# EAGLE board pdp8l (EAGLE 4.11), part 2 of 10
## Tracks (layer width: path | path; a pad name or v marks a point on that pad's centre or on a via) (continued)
B_BK  (via drill 0.61) (continued)
  Route2 0.203: v319.84,229.06 329.59,238.81 329.59,240.44 330,240.84 330,242.06 331.62,243.69 A10.L2 | v340.97,108.76 327.96,95.76 v327.56,95.76
  Route15 0.203: v336.91,86.41 v327.56,95.76 322.68,100.63 322.68,104.29 C11.M2 | v352.75,174.19 352.75,174.6 329.18,198.17 328.78,198.17 327.96,198.98 327.96,199.39 322.27,205.08 322.27,211.58 305.61,228.24 306.43,229.06 308.86,229.06 A12.S2
  Bottom 0.203: v319.84,229.06 318.21,227.43 310.9,227.43 310.08,228.24 A12.S2 | v336.91,86.41 338.94,84.38 355.6,84.38 356.01,84.78 359.26,84.78 360.07,83.97 365.76,83.97 366.98,82.75 369.42,82.75 C07.V2 | v346.66,150.22 346.25,150.62 343.81,150.62 342.6,149.4 v342.6,147.78
B_CA  (via drill 0.61)
  Top 0.203: v310.49,249.78 310.9,249.38 310.9,246.94 309.68,245.72 309.68,242.06 A12.M2 | v338.12,248.56 338.12,244.91 A10.L1 | v425.09,51.46 425.09,10.82 427.13,10.82 428.35,12.04 428.35,12.45 432.82,12.45 D02.V2 | v419,135.59 419,161.59 416.15,164.44 416.15,172.57 419.4,175.82 419.4,204.67 420.22,205.49 420.22,214.83 v419.81,215.24
  Route2 0.203: v425.09,51.46 425.09,53.09 434.85,62.84 434.85,68.53 v452.73,86.41 | v343.81,247.75 343.41,247.75 341.78,246.13 340.56,246.13 338.94,244.5 A10.L1
  Route15 0.203: v452.73,86.41 452.73,86.82 451.1,88.44 451.1,101.04 419.4,132.74 419.4,135.18 v419,135.59 | v419.81,215.24 415.75,219.3 415.75,219.71 399.08,236.37 394.21,236.37 v383.64,246.94
  Bottom 0.203: v310.49,249.78 310.9,249.38 337.31,249.38 v338.12,248.56 | v383.64,246.94 383.24,246.53 379.98,246.53 379.58,246.13 370.23,246.13 367.39,248.97 347.07,248.97 345.85,247.75 v343.81,247.75
B_EXECUTE  (via drill 0.61)
  Top 0.203: A12.N1 312.52,238.81 311.71,239.62 311.71,243.28 311.3,243.69 311.3,255.88 309.68,257.5 309.68,259.54 A12.E2 309.27,261.16 308.05,262.38 308.05,266.45 303.99,266.45 A13.C1 | 330.4,248.16 330.4,259.94 331.62,261.16 331.62,262.79 A10.D2 | 330.4,228.65 330.4,248.16 | 330.4,228.65 330.4,218.49 331.62,217.27 331.62,202.23 330.4,201.02 330.4,192.89 330.81,192.48 330.81,188.82 331.62,188.01 B10.F2 | 330.4,248.16 v330.81,248.16 | 330.4,228.65 v330.81,228.65 | v336.91,35.2 336.5,35.61 336.5,71.78 v336.91,72.19 | v323.09,73.41 323.49,73.81 323.49,88.85 322.27,90.07 322.27,91.29 C11.S2 | v307.24,128.68 307.64,128.27 307.64,109.98 306.43,108.76 C12.L2 | v343,151.84 343,151.03 348.29,151.03 349.5,152.25 349.5,168.91 350.32,169.72 350.32,174.19 B09.L1 | v283.67,131.93 285.29,131.93 285.29,128.68 v285.29,128.27
  Route2 0.203: v330.81,228.65 329.18,228.65 A11.S1 | v285.29,128.27 284.48,127.46 284.48,124.61 C14.E2 | v343,151.84 342.6,151.84 341.78,151.03 337.72,151.03 336.91,150.22 336.91,149.4 323.49,135.99 323.49,135.59 v322.27,134.37
  Route15 0.203: A11.S1 327.96,229.06 325.93,229.06 317.81,237.19 313.74,237.19 313.33,237.59 A12.N1 | v348.29,174.6 347.88,174.6 339.75,182.73 338.53,182.73 335.69,185.57 334.06,185.57 332.44,187.2 B10.F2 | C11.S2 321.46,92.1 320.65,92.1 319.84,92.91 317.81,92.91 309.27,101.45 309.27,103.07 308.05,104.29 308.05,105.51 306.43,107.14 C12.L2 | v336.91,35.2 343.81,28.3 343.81,25.86 D09.R2
  Bottom 0.203: A13.E2 297.49,259.94 298.3,259.13 308.05,259.13 308.86,259.94 A12.E2 | v348.29,174.6 350.32,174.6 B09.L1 | v330.81,248.16 334.47,248.16 A10.K2 | v285.29,128.27 285.7,128.68 v307.24,128.68 314.15,128.68 315.37,129.9 C12.C1 | v336.91,72.19 336.5,72.59 323.9,72.59 v323.09,73.41 | v322.27,134.37 321.06,135.59 318.21,135.59 316.99,134.37 313.74,134.37 313.33,134.77 304.39,134.77 301.55,131.93 291.8,131.93 291.39,132.33 288.54,132.33 288.14,131.93 v283.67,131.93
B_FETCH  (via drill 0.61)
  Top 0.203: v304.39,207.11 v304.39,257.91 | v352.75,207.11 352.75,192.48 353.97,191.26 B09.E1 | v303.17,125.83 303.17,129.49 C13.C1 | v343.41,98.6 342.6,99.42 342.6,109.17 341.38,110.39 C10.K1 | v336.91,113.23 336.91,125.02 338.12,126.24 C10.D1 | v321.87,42.93 323.49,44.55 323.49,66.5 325.12,68.12 325.12,80.72 324.31,81.53 324.31,92.91 | 324.31,92.91 324.31,93.73 325.12,94.54 C11.R1 325.93,95.76 327.15,96.98 327.15,103.89 326.75,104.29 326.75,116.89 v326.34,117.3 | v281.63,92.1 281.63,94.13 281.23,94.54 C14.R2 | 324.31,92.91 v325.12,92.91 | v331.62,170.13 330.4,168.91 v330.4,125.83
  Route2 0.203: v351.54,191.26 338.12,177.85 335.69,177.85 B10.K2 334.87,177.04 334.87,173.38 v331.62,170.13
  Route15 0.203: 336.91,112.83 338.94,112.83 340.56,111.2 C10.K1 | 336.91,112.83 331.22,112.83 329.18,114.86 329.18,116.89 C11.H1 327.96,117.3 v326.34,117.3 | v336.91,113.23 336.91,112.83
  Bottom 0.203: v351.54,191.26 351.94,190.86 353.57,190.86 B09.E1 | v304.39,257.91 301.14,257.91 300.74,257.5 A13.F1 | v304.39,207.11 304.8,206.7 310.08,206.7 310.49,206.3 314.96,206.3 315.37,206.7 352.35,206.7 v352.75,207.11 | v303.17,125.83 303.58,125.42 330.4,125.42 | 330.4,125.42 331.22,125.42 331.62,125.83 336.91,125.83 337.72,126.64 C10.D1 | v343.41,98.6 347.07,98.6 C09.P2 | v321.87,42.93 314.55,42.93 313.33,44.15 D12.J1 | v281.63,92.1 282.85,93.32 324.71,93.32 v325.12,92.91 | v330.4,125.83 330.4,125.42
B_INHIBIT  (via drill 0.61)
  Top 0.203: 165,274.17 171.09,280.26 171.09,280.67 171.5,281.08 175.97,281.08 175.97,273.76 A23.A1 | 165,274.17 164.19,273.36 A24.A1 | v234.9,205.49 234.9,198.98 235.31,198.58 235.31,161.19 237.74,158.75 237.74,94.54 237.34,94.13 237.34,93.32 237.74,92.91 237.74,44.55 242.21,44.55 D17.J2 | v176.38,207.11 176.38,203.86 B23.A1 | 165,274.17 167.84,271.32 167.84,241.25 165,238.4 165,205.08 163.78,203.86 B24.A1
  Bottom 0.203: 176.38,205.49 166.22,205.49 164.19,203.45 B24.A1 | v234.9,205.49 176.38,205.49 | 176.38,205.49 v176.38,207.11
B_MEM_ENABLE  (via drill 0.61)
  Top 0.203: D25.N2 141.02,32.36 139.8,33.58 v139.8,52.68 139.8,53.09 139.8,99.82 141.02,101.04 C25.N2 141.02,102.26 139.8,103.48 139.8,117.3 142.65,120.14 142.65,123.8 139.8,126.64 139.8,127.46 140.61,128.27 144.27,128.27 144.27,124.61 C25.E2 | C18.D2 229.62,127.46 228.8,128.27 228.8,154.28 229.62,155.09 B18.T2 230.02,156.31 230.02,159.16 228.8,160.38 228.8,224.18 229.62,224.99 A18.T2 | A23.E2 169.88,259.54 168.66,258.32 168.66,240.44 167.03,238.81 A23.N2 166.22,237.59 165.41,236.78 165.41,200.61 157.28,192.48 157.28,191.26 B24.E2 156.46,190.04 155.65,189.23 155.65,170.13 154.43,168.91 B24.N2 | v153.62,122.58 153.62,126.24 C24.D2 | C23.D2 167.03,127.46 167.84,128.27 167.84,166.88 167.03,167.69 B23.N2
  Route15 0.203: D17.L1 249.12,38.86 249.12,40.08 234.09,55.12 232.46,55.12 230.84,56.74 D18.D2
  Bottom 0.203: D17.E1 251.97,54.3 250.75,55.52 232.05,55.52 230.84,56.74 D18.D2 229.62,56.74 228.8,55.93 219.05,55.93 218.24,56.74 D19.D2 217.02,57.56 216.21,58.37 171.91,58.37 171.09,57.56 167.44,57.56 D23.D2 166.22,57.56 165.41,58.37 155.25,58.37 154.43,57.56 D24.D2 153.21,57.15 151.18,55.12 145.9,55.12 145.09,54.3 D25.E2 143.87,53.49 140.61,53.49 v139.8,52.68 | 216.21,226.62 206.04,226.62 205.23,225.81 A20.T2 | 216.21,226.62 217.02,225.81 A19.T2 | 216.21,226.62 228.8,226.62 229.62,225.81 A18.T2 230.84,225.81 231.65,226.62 241.4,226.62 242.21,225.81 A17.T2 | C18.D2 229.62,127.46 228.8,128.27 219.46,128.27 218.24,127.05 C19.D2 217.02,127.05 213.36,127.05 212.14,128.27 168.66,128.27 167.44,127.05 C23.D2 166.22,126.64 165.41,125.83 155.25,125.83 154.43,126.64 C24.D2 | 216.21,156.72 206.04,156.72 205.23,155.91 B20.T2 | 216.21,156.72 217.02,155.91 B19.T2 | 216.21,156.72 228.8,156.72 229.62,155.91 B18.T2 | A24.E2 157.68,259.94 158.5,259.13 167.84,259.13 169.06,260.35 A23.E2 | v153.62,122.58 145.9,122.58 145.09,123.39 C25.E2 | B24.N2 154.43,167.69 155.25,166.88 164.19,166.88 165,167.69 166.22,167.69 B23.N2 | B24.E2 157.68,190.86 158.5,191.67 168.25,191.67 169.06,190.86 B23.E2
B_SET  (via drill 0.61)
  Top 0.203: v28.85,244.91 25.6,248.16 25.6,264.41 23.98,266.04 A35.C1 | v239.78,143.31 241,142.09 241,70.16 238.56,67.72 v238.56,45.36 | v314.96,46.18 314.55,45.77 314.55,24.23 315.77,23.01 D12.S1
  Route15 0.203: v138.99,243.28 201.98,180.29 202.79,180.29 v239.78,143.31
  Bottom 0.203: v28.85,244.91 30.89,242.88 138.58,242.88 v138.99,243.28 | v238.56,45.36 239.37,46.18 v314.96,46.18 | D10.T2 331.22,19.36 329.59,20.98 319.84,20.98 319.02,21.79 316.59,21.79 D12.S1
B_WC  (via drill 0.61)
  Route2 0.203: v335.28,133.96 347.88,146.56 347.88,148.18 v348.69,149
  Route15 0.203: v335.28,133.96 341.38,127.86 341.38,125.83 371.86,95.35 371.86,91.29 372.26,90.88 372.26,90.07 379.17,83.16 379.17,81.53 403.56,57.15 403.56,53.09 433.22,23.42 433.22,19.76 D02.T2 | v348.69,149 348.69,149.4 340.16,157.94 340.16,162 338.94,163.22 337.31,163.22 335.69,164.85 B10.P2
BEMA  (via drill 0.61)
  Top 0.203: v330.4,77.88 330.4,83.16 330.81,83.57 330.81,88.04 331.22,88.44 C10.T2 | v13.01,125.83 13.01,154.28 13.82,155.09 B35.T2
  Route2 0.203: v330.4,77.88 330.4,77.06 311.3,57.96 311.3,57.15 310.9,56.74 307.64,56.74 306.83,55.93 274.73,55.93 273.91,55.12 269.04,55.12 262.94,49.02 242.21,49.02 v241.81,48.62
  Route15 0.203: v178.82,49.02 133.71,94.13 133.71,96.16 132.08,97.79 C26.P2
  Bottom 0.203: v241.81,48.62 241.4,49.02 v178.82,49.02 | v13.01,125.83 13.01,122.99 12.19,122.99 8.13,118.92 4.06,118.92 3.25,118.11 3.25,96.98 13.82,96.98 16.66,99.82 26.82,99.82 29.67,96.98 39.42,96.98 42.27,99.82 115.42,99.82 118.26,96.98 130.45,96.98 131.27,97.79 C26.P2
BREAK
  Top 0.203: D10.V2 331.22,13.26 330,14.48 330,29.11 321.06,38.05 321.06,46.18 321.87,46.99 D11.H2
BREAK\  (via drill 0.61)
  Top 0.203: v116.64,111.61 116.64,109.17 116.23,108.76 C27.L2 | v339.34,67.72 339.34,14.07 338.53,13.26 D10.V1 338.53,12.04 342.19,8.38 342.19,5.13 | v372.67,68.53 373.07,68.94 373.07,85.19 C07.U2 | v441.35,31.14 440.94,30.73 440.94,18.14 423.88,1.07 342.19,1.07 342.19,5.13 | v323.49,5.13 342.19,5.13
  Route2 0.203: v441.35,31.14 445.41,35.2 445.41,37.64 D01.L2
  Route15 0.203: v235.31,5.13 186.13,54.3 184.91,54.3 164.59,74.62 164.59,76.66 162.97,78.28 162.56,78.28 128.83,112.01 128.83,113.64 C26.J2
  Bottom 0.203: v116.64,111.61 117.86,112.83 126.8,112.83 128.02,114.05 C26.J2 | v339.34,67.72 339.34,68.94 372.26,68.94 v372.67,68.53 | v235.31,5.13 235.71,5.54 246.69,5.54 247.5,6.35 260.5,6.35 262.13,4.72 292.2,4.72 293.42,5.94 301.14,5.94 302.36,4.72 323.09,4.72 v323.49,5.13
BREAK_OK
  Top 0.203: D12.R2 306.02,25.86 305.21,26.67 305.21,36.83 306.02,37.64 D12.L2 306.02,38.86 306.02,41.3 304.39,42.93 304.39,52.68 303.58,53.49 D13.E1
  Bottom 0.203: D11.M1 327.96,35.2 327.15,36.02 323.09,36.02 322.27,36.83 307.64,36.83 306.83,37.64 D12.L2
BREAK_OK\  (via drill 0.61)
  Top 0.203: v321.46,114.86 321.06,115.27 321.06,131.12 321.87,131.93 v321.87,133.15 | v303.99,95.76 304.39,95.35 304.39,70.97 303.99,70.56 303.99,68.12 304.39,67.72 304.39,58.78 v303.99,58.37
  Route2 0.203: v321.46,114.86 321.06,114.45 319.84,114.45 C11.J2 318.62,113.64 318.62,111.61 309.27,102.26 309.27,101.04 v303.99,95.76
  Bottom 0.203: v321.87,133.15 324.71,133.15 C11.B1 | D13.D1 300.74,57.56 301.55,58.37 v303.99,58.37 317.81,58.37 318.21,58.78 329.59,58.78 330,58.37 335.28,58.37 337.72,55.93 338.53,55.93 340.97,58.37 340.97,59.59 D10.C1
BRK_RQST\  (via drill 0.61)
  Top 0.203: v319.84,134.77 319.84,144.93 320.24,145.34 320.24,154.28 319.43,155.09 B11.T2
  Route2 0.203: v319.84,134.77 318.62,134.77 317.81,133.96 317.81,129.08 316.18,127.46 316.18,126.24 308.05,118.11 308.05,114.05 288.54,94.54 288.54,93.73 284.48,89.66 282.85,89.66 277.57,94.94 269.04,86.41 267.82,86.41 262.53,81.13 243.84,81.13 175.97,13.26 v175.56,13.26
  Route15 0.203: D29.T2 89.81,19.36 87.38,19.36 41.05,65.68 41.05,66.5 36.58,70.97 36.58,81.53 8.94,109.17 6.91,109.17 5.28,110.79 C36.K2
  Bottom 0.203: v175.56,13.26 173.13,10.82 101.6,10.82 93.88,18.54 91.03,18.54 D29.T2
BTP2  (via drill 0.61)
  Top 0.203: v401.12,36.02 403.15,36.02 403.15,42.52 401.93,43.74 D05.J1
  Route15 0.203: v47.14,150.62 47.14,150.22 47.55,149.81 47.55,146.56 v153.21,40.89 | v316.59,32.77 321.06,37.24 321.87,36.42 331.62,36.42 v332.44,35.61
  Bottom 0.203: v47.14,150.62 25.6,150.62 25.6,154.28 26.42,155.09 B34.T2 | v153.21,40.89 157.68,36.42 236.12,36.42 242.21,30.33 264.97,30.33 267.82,33.17 303.58,33.17 303.99,33.58 310.08,33.58 310.49,33.17 316.18,33.17 v316.59,32.77 | v332.44,35.61 333.25,36.42 350.72,36.42 353.57,33.58 388.93,33.58 391.77,36.42 400.71,36.42 v401.12,36.02
BTP3  (via drill 0.61)
  Top 0.203: v212.55,66.5 200.76,78.28 v200.76,79.91
  Route15 0.203: v335.28,64.47 347.07,52.68 348.69,52.68 349.1,52.27 351.54,52.27 365.76,38.05 371.86,44.15 375.51,44.15 D07.J1 | v102.82,87.22 54.05,135.99 54.05,137.62 34.95,156.72 34.95,158.34 13.01,180.29 13.01,181.91 11.38,183.54 B36.H1
  Bottom 0.203: v335.28,64.47 334.87,64.87 330,64.87 327.56,62.43 326.34,62.43 325.93,62.03 317.4,62.03 316.99,62.43 313.74,62.43 313.33,62.03 304.39,62.03 303.99,62.43 301.14,62.43 300.74,62.03 291.8,62.03 291.39,62.43 288.14,62.43 287.73,62.03 279.2,62.03 278.79,62.43 275.54,62.43 275.13,62.03 266.6,62.03 266.19,62.43 262.94,62.43 262.53,62.03 254,62.03 251.16,64.87 241,64.87 240.59,64.47 237.74,64.47 236.93,65.28 213.77,65.28 v212.55,66.5 | v200.76,79.91 126.8,79.91 119.48,87.22 v102.82,87.22
C01V1  (via drill 0.61)
  Top 0.508: v450.7,140.46 450.7,84.38 451.92,83.16 C01.V1 | v108.1,140.46 107.7,140.87 107.7,206.7 104.85,209.55 104.85,229.87 103.63,231.09 A28A.R2
  Bottom 0.508: v450.7,140.46 450.29,140.87 209.3,140.87 208.89,140.46 v108.1,140.46
CA_INCREMENT  (via drill 0.61)
  Top 0.203: v16.26,140.46 16.26,123.39 18.69,120.95 18.69,106.32 17.88,105.51 C35.M2 | v42.67,166.88 42.67,170.94 B33.M2 | v102.01,274.98 101.19,274.17 101.19,232.31 v100.38,231.5
  Route2 0.203: v16.26,140.46 16.26,140.87 20.73,145.34 21.13,145.34 v42.67,166.88 | v100.38,231.5 100.38,231.09 89.81,220.52 88.59,220.52 76.4,208.33 76.4,207.11 44.7,175.41 44.7,173.79 43.08,172.16 B33.M2
  Route15 0.203: v232.05,277.01 244.25,264.82 262.53,264.82 263.75,263.6 264.57,263.6 266.19,261.98 267.82,261.98 280.82,248.97 290.98,248.97 294.23,245.72 300.74,245.72 301.95,244.5 305.61,244.5 A12.L2
  Bottom 0.203: v232.05,277.01 231.65,277.42 175.16,277.42 174.35,276.61 156.06,276.61 154.84,275.39 102.41,275.39 v102.01,274.98
CARRY_INSERT  (via drill 0.61)
  Top 0.203: v249.94,195.73 245.06,200.61 245.06,202.23 241.4,205.89 241.4,266.45 v247.9,272.95 | v288.54,276.2 292.2,276.2 v292.2,273.76 | v433.22,273.36 440.94,265.63 440.94,216.86 440.54,216.46 440.54,201.42 440.94,201.02 440.94,182.32 440.13,181.51 AB02.BJ1
  Route15 0.203: v277.57,169.32 268.63,178.26 268.63,178.66 268.22,179.07 266.6,179.07 v249.94,195.73 | v364.54,275.39 373.89,284.73 421.84,284.73 v433.22,273.36
  Bottom 0.203: v277.57,169.32 277.98,169.72 291.8,169.72 293.01,168.5 B13.N2 | v247.9,272.95 249.94,274.98 276.35,274.98 277.57,276.2 v288.54,276.2 | v292.2,273.76 293.01,274.57 320.24,274.57 320.65,274.98 334.47,274.98 336.09,276.61 355.6,276.61 356.82,275.39 v364.54,275.39
CARRYOUT0  (via drill 0.61)
  Top 0.203: v321.06,79.1 321.06,55.52 321.87,54.71 D11.E2 | v345.44,105.1 345.85,105.51 345.85,117.3 346.25,117.7 346.25,145.34 341.78,149.81 341.78,151.84 B10.U1 | v295.45,233.93 295.05,234.34 295.05,244.91 292.2,247.75 292.2,255.88 293.01,256.69 A13.F2 | v306.02,222.15 307.64,220.52 307.64,213.61 307.24,213.21 307.24,201.42 307.64,201.02 307.64,194.92 306.83,194.11 B12.D2
  Route2 0.203: v321.06,79.1 323.09,81.13 323.09,83.16 345.03,105.1 v345.44,105.1
  Route15 0.203: B12.D2 306.43,192.89 306.43,191.67 338.12,159.97 338.12,157.53 339.34,156.31 339.34,154.69 340.97,153.06 B10.U1 | v295.45,233.93 295.45,232.72 v306.02,222.15
CARRYOUT0\  (via drill 0.61)
  Route2 0.203: B10.U2 335.69,152.65 337.31,152.65 342.19,157.53 344.22,157.53 v345.44,158.75 346.66,159.97 350.72,159.97 357.23,166.47 359.66,166.47 369.01,175.82 370.64,175.82 372.26,177.44 AB07.BK2
  Route15 0.203: v345.44,158.75 339.34,164.85 339.34,169.32 338.94,169.72 338.53,169.72 330.4,177.85 330.4,179.07 316.18,193.29 316.18,196.14 B12.C1
CARRYOUT6\
  Bottom 0.203: AB05.BJ1 402.34,180.7 403.96,179.07 409.65,179.07 410.46,178.26 AB04.BK2
CLOCK1  (via drill 0.61)
  Top 0.203: v82.09,181.51 82.09,160.38 81.28,159.56 AB30.BS2 | v91.44,185.98 91.85,186.38 91.85,194.92 91.44,195.33 91.44,198.98 91.85,199.39 91.85,206.7 89.41,209.14 89.41,216.05 93.07,219.71 93.07,221.74 AB29.AU2
  Bottom 0.203: v82.09,181.51 86.56,185.98 v91.44,185.98
CLOCK_SCALE2
  Top 0.203: D32.T2 52.83,19.76 54.05,20.98 54.05,26.67 55.27,27.89 D32.P2
CLR_PARITY_ERROR\  (via drill 0.61)
  Top 0.203: v285.29,240.03 v285.29,195.33
  Route2 0.203: v285.29,195.33 271.07,181.1 269.04,181.1 B15.J2
  Bottom 0.203: v285.29,240.03 286.51,241.25 289.76,241.25 A14.M1
CONTROL_IOT  (via drill 0.61)
  Top 0.203: v287.73,105.51 285.7,107.54 285.7,126.24 286.11,126.64 v286.11,138.02
  Route2 0.203: v286.11,138.02 304.8,156.72 304.8,159.97 306.02,161.19 B12.R2
  Bottom 0.203: v287.73,105.51 288.14,105.92 295.45,105.92 296.27,105.1 C13.M2
CURRENT_ADDR\  (via drill 0.61)
  Top 0.203: v434.44,41.71 434.85,41.3 434.85,17.73 436.07,16.51 D02.U2 | D12.R1 313.33,25.86 314.15,26.67 314.15,36.83 313.33,37.64 D12.L1 | v340.16,23.42 340.16,17.32 340.97,16.51 D10.U1
  Route15 0.203: v169.47,78.28 169.06,78.28 132.08,115.27 132.08,116.89 C26.H2 | v282.04,70.97 310.9,42.11 310.9,40.49 312.52,38.86 D12.L1
  Bottom 0.203: v434.44,41.71 435.25,42.52 447.85,42.52 448.67,41.71 D01.K2 | v169.47,78.28 177.6,70.16 281.23,70.16 v282.04,70.97 | v340.16,23.42 339.34,24.23 314.15,24.23 313.33,25.04 D12.R1 | D02.U2 436.07,15.29 435.25,14.48 347.07,14.48 346.25,15.29 341.78,15.29 D10.U1
CYC_DONE  (via drill 0.61)
  Top 0.203: D16.N1 262.13,32.36 263.75,33.98 263.75,45.77 264.97,46.99 D16.H1 | v279.2,50.65 279.6,51.05 279.6,55.12 279.2,55.52 279.2,103.48 278.38,104.29 C15.M1
  Route15 0.203: C15.M1 277.57,105.51 277.57,107.14 272.29,112.42 270.66,112.42 269.04,114.05 C15.J2 | D16.L2 256.03,37.64 256.03,35.61 258.06,33.58 259.69,33.58 261.31,31.95 D16.N1
  Bottom 0.203: D16.H1 265.79,47.8 269.04,47.8 270.66,49.43 272.69,49.43 273.91,50.65 D15.F1 275.13,50.65 v279.2,50.65
CYCLE  (via drill 0.61)
  Top 0.203: v267.82,49.02 270.26,49.02 270.26,119.33 271.07,120.14 271.07,123.39 C15.E2
  Bottom 0.203: v267.82,49.02 260.1,49.02 259.28,48.21 D16.H2
D01V1  (via drill 0.61)
  Top 0.508: v114.61,141.68 114.61,216.46 106.88,224.18 106.88,227.43 106.48,227.84 A28A.S2 | v442.16,142.09 444.19,140.06 444.19,14.07 443.79,13.66 443.79,11.23 444.6,10.41 451.92,10.41 451.92,12.45 D01.V1
  Bottom 0.508: v114.61,141.68 115.01,141.28 208.48,141.28 208.89,141.68 441.76,141.68 v442.16,142.09
D_SET
  Route15 0.203: C07.R2 369.42,95.76 369.01,95.76 366.98,97.79 C08.P1
D_SET\  (via drill 0.61)
  Top 0.203: v324.31,118.52 324.31,125.42 325.12,126.24 C11.D1 | v317.81,186.38 317.81,148.59 316.99,147.78 316.99,137.62 317.4,137.21 317.4,127.46 v316.99,127.05
  Route2 0.203: v324.31,118.52 323.9,118.11 322.68,118.11 C11.H2 | v357.23,99.42 351.54,93.73 349.5,93.73 348.29,92.51 C09.S2
  Route15 0.203: v317.81,186.38 303.58,200.61 303.58,202.64 B13.A1 | C09.S2 347.07,92.51 347.07,96.16 343.81,99.42 342.19,99.42 325.12,116.48 325.12,117.3 324.31,118.11 v324.31,118.52
  Bottom 0.203: v316.99,127.05 318.21,125.83 323.9,125.83 324.71,126.64 C11.D1 | v357.23,99.42 357.63,99.82 371.04,99.82 372.26,98.6 C07.P2
DATA00  (via drill 0.61)
  Top 0.203: v37.8,276.2 35.36,273.76 35.36,255.47 36.17,254.66 A34.H1 | v351.54,275.39 353.97,275.39 353.97,274.98 356.01,272.95 356.01,266.85 361.7,261.16 v361.7,233.93 | v373.07,176.22 373.07,172.16 AB07.BM2
  Route2 0.203: v259.28,232.31 260.1,232.31 262.94,235.15 263.35,235.15 272.29,244.09 272.29,244.91 276.76,249.38 276.76,249.78 277.17,250.19 278.38,250.19 283.67,255.47 296.27,255.47 315.37,274.57 327.15,274.57 327.56,274.98 336.91,274.98 337.31,275.39 v351.54,275.39 | v361.7,233.93 361.29,233.93 360.48,233.12 360.48,230.68 365.76,225.4 358.04,217.68 356.82,217.68 355.19,216.05 355.19,214.83 v353.16,212.8
  Route15 0.203: v148.34,277.42 208.08,277.42 220.27,265.23 224.74,265.23 251.56,238.4 253.19,238.4 v259.28,232.31 | v353.16,212.8 353.16,210.77 358.85,205.08 360.48,205.08 361.7,203.86 361.7,198.98 374.29,186.38 374.29,180.7 v375.92,179.07
  Bottom 0.203: v37.8,276.2 39.01,277.42 v148.34,277.42 | v375.92,179.07 375.92,176.22 v373.07,176.22
DATA01  (via drill 0.61)
  Top 0.203: v383.24,277.83 377.95,277.83 377.95,277.42 376.73,276.2 371.04,276.2 371.04,278.23 365.76,283.52 309.27,283.52 309.27,279.45 305.61,275.79 v305.61,273.76 | v40.64,268.07 38.2,265.63 38.2,249.38 36.98,248.16 A34.K1
  Route2 0.203: v427.13,227.03 426.72,227.03 425.09,225.4 425.09,221.74 423.88,220.52 423.88,216.86 419,211.99 419,208.33 379.98,169.32 379.17,169.32 375.51,165.66 373.48,165.66 AB07.BP2 | v305.61,273.76 305.61,273.36 303.99,271.73 291.39,271.73 278.79,259.13 273.1,259.13 v258.06,244.09
  Route15 0.203: v427.13,227.03 427.13,229.87 425.91,231.09 425.91,236.37 416.15,246.13 414.93,246.13 v383.24,277.83 | v258.06,244.09 227.58,274.57 226.37,274.57 v224.74,276.2
  Bottom 0.203: v224.74,276.2 224.33,275.79 205.64,275.79 205.23,276.2 175.56,276.2 175.16,275.79 160.12,275.79 158.9,274.57 103.63,274.57 102.82,273.76 101.19,273.76 100.38,274.57 71.12,274.57 70.31,273.76 69.49,273.76 68.68,274.57 47.14,274.57 v40.64,268.07
DATA02  (via drill 0.61)
  Top 0.203: v40.64,241.25 36.98,241.25 A34.M1 | v169.06,279.86 170.69,281.48 230.02,281.48 230.02,278.23 230.43,277.83 231.65,277.83 231.65,283.11 250.75,283.11 v250.75,273.36 | v269.04,273.76 269.85,274.57 269.85,277.83 v271.88,279.86 | v392.58,278.23 402.74,278.23 403.15,277.83 412.9,277.83 412.9,279.04 413.31,279.45 419.4,279.45 419.4,254.25 421.84,251.82 421.84,218.49 422.25,218.08 422.25,211.18 v422.66,210.77
  Route2 0.203: v40.64,241.25 43.48,238.4 45.11,240.03 45.92,240.03 48.36,242.47 53.24,242.47 68.68,257.91 69.49,257.91 76.81,265.23 105.26,265.23 122.73,247.75 130.86,255.88 131.67,255.88 150.37,274.57 154.84,274.57 160.12,279.86 v169.06,279.86 | v271.88,279.86 272.69,280.67 273.91,280.67 275.95,282.7 301.14,282.7 301.95,283.52 318.21,283.52 326.75,274.98 327.15,275.39 334.47,275.39 335.69,276.61 364.95,276.61 367.39,274.17 369.01,275.79 382.42,275.79 384.86,278.23 v392.58,278.23 | v422.66,210.77 422.66,210.36 387.71,175.41 387.71,173.79 386.08,172.16 AB06.BM2
  Bottom 0.203: v250.75,273.36 251.97,274.57 268.22,274.57 v269.04,273.76
DATA03  (via drill 0.61)
  Top 0.203: v315.37,150.22 317.4,150.22 317.4,161.19 v316.99,161.59
  Route2 0.203: v158.5,232.72 193.85,268.07 v194.26,268.07 | v325.12,163.63 325.12,165.25 327.15,167.28 327.15,168.1 330,170.94 330,173.79 328.37,175.41 333.25,180.29 333.25,184.35 334.47,185.57 338.94,185.57 v341.38,188.01
  Route15 0.203: v194.26,268.07 210.11,268.07 260.91,217.27 263.35,217.27 266.6,214.02 266.6,204.67 267,204.27 267,199.39 278.79,187.6 279.2,187.6 279.6,187.2 279.6,185.57 304.8,160.38 304.8,159.16 310.9,153.06 311.71,153.06 313.74,151.03 314.55,151.03 v315.37,150.22 | v362.1,185.57 362.1,184.76 376.73,170.13 378.76,170.13 382.02,166.88 384.05,166.88 385.27,165.66 AB06.BP2
  Bottom 0.203: v158.5,232.72 158.09,233.12 70.71,233.12 69.49,231.9 67.46,231.9 66.24,233.12 58.12,233.12 57.71,232.72 56.08,232.72 55.68,233.12 38.2,233.12 36.98,234.34 A34.P1 | v316.99,161.59 319.02,163.63 v325.12,163.63 | v341.38,188.01 342.19,188.82 358.85,188.82 v362.1,185.57
DATA04  (via drill 0.61)
  Top 0.203: v419.4,11.23 422.66,11.23 422.66,51.05 v423.47,51.87 | v383.64,121.77 384.05,122.17 384.05,138.43 384.45,138.84 384.45,159.56 385.27,160.38 v385.67,160.38
  Route2 0.203: v385.67,160.38 388.52,163.22 392.18,163.22 396.65,167.69 396.65,169.72 397.87,170.94 AB05.BM2
  Route15 0.203: v306.43,7.98 303.17,4.72 302.36,4.72 301.95,5.13 297.89,5.13 294.23,8.79 292.61,8.79 290.17,11.23 286.92,11.23 271.07,27.08 264.57,27.08 258.47,33.17 257.66,33.17 255.63,35.2 254.81,35.2 253.19,36.83 248.31,36.83 217.02,68.12 209.7,68.12 170.69,107.14 170.28,107.14 142.24,135.18 137.36,135.18 124.77,147.78 121.51,147.78 78.03,191.26 76,191.26 60.55,206.7 57.71,206.7 57.3,207.11 56.49,207.11 50.8,212.8 50.8,213.21 47.55,216.46 47.55,219.71 39.01,228.24 36.98,228.24 A34.S1 | v423.47,51.87 423.47,52.27 422.66,53.09 422.66,73.81 418.19,78.28 416.56,78.28 412.9,81.94 412.9,86.82 397.46,102.26 397.05,102.26 396.65,102.67 396.65,104.29 384.45,116.48 384.45,120.95 v383.64,121.77
  Bottom 0.203: v306.43,7.98 308.46,10.01 385.67,10.01 386.89,11.23 v419.4,11.23
DATA05  (via drill 0.61)
  Top 0.203: v399.49,176.63 399.9,176.22 399.9,166.88 398.68,165.66 AB05.BP2 | v246.69,144.12 244.65,142.09 v244.65,118.52 | v36.98,194.51 37.8,195.33 37.8,204.67 36.17,206.3 36.17,221.74 A34.U1
  Route2 0.203: v399.49,176.63 386.49,163.63 384.86,163.63 379.58,168.91 375.92,165.25 375.11,165.25 373.48,163.63 369.42,163.63 365.35,159.56 365.35,155.5 357.23,147.37 356.82,147.37 356.41,146.96 356.41,144.93 v349.5,138.02 | v322.68,162.41 322.68,161.59 311.3,150.22 311.3,147.37 309.27,145.34 308.05,145.34 306.43,143.71 306.43,142.9 306.02,142.49 303.17,142.49 299.92,139.24 299.92,135.99 294.64,130.71 294.64,129.9 v294.23,129.49
  Route15 0.203: v349.5,138.02 349.1,138.02 348.69,138.43 347.47,138.43 338.12,147.78 337.72,147.78 336.91,148.59 336.91,154.28 330,161.19 328.78,161.19 327.15,159.56 325.53,159.56 v322.68,162.41 | v294.23,129.49 294.23,130.71 289.36,135.59 289.36,137.62 v283.67,143.31 | v116.23,116.08 94.28,138.02 91.03,138.02 54.05,175.01 54.05,176.63 39.42,191.26 39.42,192.07 v36.98,194.51
  Bottom 0.203: v283.67,143.31 283.26,143.71 254.81,143.71 254,142.9 249.53,142.9 248.31,144.12 v246.69,144.12 | v244.65,118.52 241.81,115.67 217.02,115.67 216.61,116.08 206.45,116.08 206.04,116.48 202.79,116.48 202.39,116.08 179.63,116.08 176.78,118.92 145.09,118.92 141.83,122.17 127.61,122.17 121.51,116.08 v116.23,116.08
DATA06  (via drill 0.61)
  Top 0.203: v72.34,281.89 71.12,280.67 71.12,280.26 38.2,280.26 33.33,275.39 33.33,274.17 28.85,269.7 28.85,259.54 27.23,257.91 A34.F2
  Route2 0.203: v297.89,121.77 298.3,121.77 302.36,125.83 302.36,126.24 302.77,126.64 304.39,126.64 305.21,127.46 305.21,127.86 315.77,138.43 316.18,138.43 325.53,147.78 325.93,147.78 v327.56,149.4 | v336.5,147.78 340.16,147.78 347.07,154.69 347.88,154.69 356.41,163.22 360.88,163.22 v362.51,164.85
  Route15 0.203: v72.34,281.89 74.37,281.89 74.78,281.48 97.94,281.48 101.6,277.83 145.9,277.83 147.52,276.2 149.96,276.2 202.79,223.37 204.83,223.37 213.36,214.83 213.77,214.83 215.39,213.21 215.39,211.18 248.31,178.26 248.31,177.44 280.01,145.75 280.01,145.34 286.92,138.43 286.92,135.59 284.89,133.55 295.86,122.58 297.08,122.58 v297.89,121.77 | v362.51,164.85 v359.66,167.69
  Bottom 0.203: v327.56,149.4 327.96,149 330,149 331.22,147.78 v336.5,147.78 | v359.66,167.69 361.7,169.72 390.14,169.72 390.55,169.32 394.21,169.32 395.02,170.13 409.25,170.13 410.46,171.35 AB04.BM2
DATA07  (via drill 0.61)
  Route2 0.203: v145.9,278.64 145.09,279.45 101.6,279.45 100.38,278.23 73.15,278.23 71.12,276.2 68.68,276.2 67.87,275.39 67.06,275.39 66.65,274.98 60.96,274.98 58.52,272.54 56.9,272.54 56.08,271.73 38.61,271.73 38.2,271.32 32.92,271.32 28.45,266.85 28.45,256.69 27.23,255.47 27.23,251.41 A34.J2 | v338.12,139.24 338.12,139.65 355.6,157.12 355.6,157.53 356.01,157.94 357.63,157.94 385.27,185.57 388.11,185.57 v388.52,185.17
  Route15 0.203: v145.9,278.64 147.93,276.61 206.45,276.61 213.36,269.7 214.99,269.7 219.86,264.82 220.68,264.82 244.65,240.84 244.65,240.44 267.41,217.68 269.85,217.68 279.6,207.92 281.63,207.92 298.3,191.26 298.3,190.45 299.11,189.64 299.11,188.82 297.89,187.6 299.52,185.98 299.92,185.98 300.33,185.57 300.33,184.76 v305.21,179.88 | v300.33,177.04 324.31,153.06 325.12,153.06 328.37,149.81 328.37,149 v338.12,139.24 | v388.52,185.17 406.81,166.88 408.84,166.88 410.46,165.25 AB04.BP2
  Bottom 0.203: v305.21,179.88 304.39,179.07 302.36,179.07 v300.33,177.04
DATA08  (via drill 0.61)
  Top 0.203: v403.96,161.59 406.4,164.03 v406.4,169.32
  Route2 0.203: v98.75,270.1 91.85,277.01 74.37,277.01 69.09,271.73 67.87,271.73 67.46,271.32 64.62,271.32 61.37,268.07 58.93,268.07 39.83,248.97 29.67,248.97 27.64,246.94 27.64,244.91 A34.L2
  Route15 0.203: v165,270.1 171.09,276.2 202.79,276.2 261.31,217.68 263.75,217.68 v269.85,211.58 | v294.23,207.52 294.64,207.52 295.45,206.7 303.58,206.7 303.99,206.3 309.68,206.3 316.18,199.8 317.4,199.8 318.62,198.58 324.71,198.58 346.66,176.63 347.47,176.63 349.1,175.01 349.1,174.19 v357.63,165.66
  Bottom 0.203: v98.75,270.1 99.16,270.51 101.6,270.51 102.41,271.32 161.34,271.32 162.56,270.1 v165,270.1 | v269.85,211.58 273.91,207.52 v294.23,207.52 | v357.63,165.66 359.66,163.63 373.48,163.63 374.7,164.85 376.73,164.85 378.36,163.22 402.34,163.22 v403.96,161.59 | v406.4,169.32 406.81,169.72 421.44,169.72 423.06,171.35 AB03.BM2
DATA09  (via drill 0.61)
  Route2 0.203: v17.48,225.4 26.42,234.34 26.42,237.59 A34.N2 | v290.98,6.35 310.49,6.35 327.56,23.42 333.25,23.42 333.65,23.83 334.47,23.83 365.35,54.71 365.35,55.52 379.58,69.75 380.39,69.75 v388.52,77.88 | v361.29,114.05 378.76,131.52 383.64,131.52 390.55,138.43 395.02,138.43 419.81,163.22 421.44,163.22 423.06,164.85 AB03.BP2
  Route15 0.203: v17.48,225.4 17.48,224.18 18.69,222.96 18.69,198.58 25.6,191.67 25.6,190.86 34.54,181.91 34.54,177.85 48.77,163.63 v54.86,163.63 | v87.38,160.78 98.35,149.81 98.35,148.18 172.72,73.81 173.53,73.81 220.27,27.08 256.03,27.08 257.25,25.86 259.28,25.86 260.91,24.23 272.29,24.23 286.11,10.41 286.92,10.41 v290.98,6.35 | v388.52,77.88 388.52,80.72 384.45,84.78 384.45,85.19 372.67,96.98 372.26,96.98 371.86,97.38 371.86,102.26 367.39,106.73 367.39,107.14 366.98,107.54 366.98,108.36 v361.29,114.05
  Bottom 0.203: v54.86,163.63 55.27,163.22 66.24,163.22 69.09,160.38 86.97,160.38 v87.38,160.78
DATA10  (via drill 0.61)
  Top 0.203: v434.44,98.6 434.85,98.2 434.85,69.75 v434.44,69.34
  Route2 0.203: v434.44,98.6 440.54,104.7 440.54,105.92 444.6,109.98 444.6,121.36 447.85,124.61 447.85,168.5 446.63,169.72 445.41,169.72 443.79,168.1 440.54,171.35 437.29,171.35 AB02.BM2 | v434.44,69.34 434.44,66.5 v369.82,1.88 | v23.98,219.71 21.54,222.15 v30.07,230.68
  Route15 0.203: v369.82,1.88 369.01,1.07 244.65,1.07 118.67,127.05 117.86,127.05 106.88,138.02 104.04,138.02 75.18,166.88 75.18,167.28 28.04,214.43 27.64,214.43 27.23,214.83 27.23,216.46 v23.98,219.71
  Bottom 0.203: v30.07,230.68 29.26,231.5 27.64,231.5 A34.R2
DATA11  (via drill 0.61)
  Top 0.203: v432.82,118.11 435.25,120.55 435.25,163.63 436.07,164.44 AB02.BP2 | v428.75,114.05 428.35,113.64 428.35,98.6 425.91,96.16 425.91,92.1 v426.31,91.69
  Route2 0.203: v426.31,91.69 425.5,90.88 425.5,85.19 418.59,78.28 418.59,72.59 416.56,70.56 415.75,70.56 415.34,70.16 411.28,70.16 387.71,46.58 387.71,46.18 v354.79,13.26
  Route15 0.203: v293.01,9.6 292.61,9.6 272.29,29.92 267.41,29.92 266.6,30.73 265.38,30.73 158.5,137.62 157.68,137.62 147.52,147.78 147.12,147.78 127.2,167.69 127.2,171.75 91.44,207.52 91.03,207.52 v80.87,217.68
  Bottom 0.203: v428.75,114.05 v432.82,118.11 | v354.79,13.26 351.94,10.41 303.99,10.41 303.17,9.6 v293.01,9.6 | v80.87,217.68 74.78,217.68 68.68,223.77 63.8,223.77 62.99,224.59 60.15,224.59 59.74,224.18 55.68,224.18 53.24,226.62 49.99,226.62 47.55,224.18 28.45,224.18 27.64,224.99 A34.T2
DATA_ADD00  (via drill 0.61)
  Top 0.203: v398.68,82.75 400.3,84.38 v400.3,105.1 | v399.9,107.54 400.3,107.95 400.3,116.08 403.56,119.33 403.56,157.12 v402.74,157.94
  Route2 0.203: v398.68,82.75 372.67,56.74 371.45,56.74 368.61,53.9 368.61,53.09 338.94,23.42 334.06,23.42 333.25,22.61 329.18,22.61 D11.S1 | v400.3,105.1 400.3,107.14 v399.9,107.54
  Bottom 0.203: v402.74,157.94 402.34,157.53 380.8,157.53 379.98,158.34 AB07.BS1
DATA_ADD01  (via drill 0.61)
  Top 0.203: v360.07,51.87 361.7,53.49 361.7,70.16 359.26,72.59 359.26,82.35 365.35,88.44 v365.35,94.94 | v380.39,127.46 380.8,127.86 380.8,151.03 379.98,151.84 AB07.BU1
  Route2 0.203: v360.07,51.87 357.23,49.02 353.16,49.02 327.96,23.83 327.15,23.83 325.93,22.61 322.68,22.61 D11.S2 | v365.35,94.94 365.76,94.94 380.8,109.98 380.8,115.27 381.2,115.67 381.2,126.64 v380.39,127.46
DATA_ADD02  (via drill 0.61)
  Top 0.203: v390.96,137.62 391.36,138.02 391.36,149.81 393.39,151.84 393.39,156.72 392.18,157.94 AB06.BS1
  Route2 0.203: v394.21,73 331.22,10.01 327.15,10.01 324.71,7.57 319.84,12.45 D11.V2 | v369.01,111.61 369.82,111.61 374.29,116.08 374.29,122.58 380.8,129.08 382.42,129.08 v390.96,137.62
  Route15 0.203: v394.21,73 389.33,77.88 389.33,80.31 391.36,82.35 382.42,91.29 382.42,92.51 371.45,103.48 371.45,109.17 v369.01,111.61
DATA_ADD03  (via drill 0.61)
  Top 0.203: v390.96,170.13 390.96,153.87 391.77,153.06 AB06.BU1
  Route15 0.203: v331.62,172.16 v325.12,178.66
  Bottom 0.203: v390.96,170.13 349.5,170.13 349.1,169.72 334.06,169.72 v331.62,172.16 | v325.12,178.66 324.71,179.07 317.4,179.07 316.59,178.26 B12.K1
DATA_ADD04  (via drill 0.61)
  Top 0.203: v301.14,49.43 301.55,49.84 301.55,61.62 300.33,62.84 D13.B1 | v408.84,118.52 409.25,118.92 409.25,127.46 406.81,129.9 406.81,155.91 404.77,157.94 AB05.BS1
  Route2 0.203: v375.92,75.44 374.29,77.06 375.11,77.88 375.11,79.5 380.8,85.19 380.8,90.47 404.77,114.45 405.18,114.45 408.84,118.11 v408.84,118.52
  Route15 0.203: v365.35,48.62 371.04,54.3 368.61,56.74 368.61,60 379.98,71.37 v375.92,75.44
  Bottom 0.203: v301.14,49.43 301.55,49.02 317.4,49.02 320.24,46.18 356.82,46.18 359.66,49.02 364.95,49.02 v365.35,48.62
DATA_ADD05  (via drill 0.61)
  Top 0.203: v304.39,25.86 304.39,39.68 303.58,40.49 D13.K1 | v405.59,138.02 405.18,138.43 405.18,151.84 AB05.BU1
  Route2 0.203: v304.39,25.86 304.39,26.26 306.43,28.3 307.24,28.3 318.21,39.27 321.06,39.27 321.46,39.68 324.71,39.68 325.93,40.89 325.93,42.93 333.65,50.65 335.28,50.65 338.94,54.3 339.75,54.3 340.56,55.12 351.94,55.12 v371.04,74.22 | v382.02,77.47 382.02,78.28 391.77,88.04 391.77,88.85 398.27,95.35 398.27,96.16 405.99,103.89 405.99,107.95 v417.37,119.33
  Route15 0.203: v417.37,119.33 417.37,121.77 409.65,129.49 409.65,133.96 v405.59,138.02
  Bottom 0.203: v371.04,74.22 374.29,77.47 v382.02,77.47
DATA_ADD06  (via drill 0.61)
  Route2 0.203: v361.29,13.66 361.7,13.66 412.9,64.87 412.9,66.09 419,72.19 419,77.88 425.91,84.78 425.91,85.6 431.6,91.29 431.6,97.79 444.19,110.39 444.19,131.12 436.47,138.84 v436.07,138.43
  Route15 0.203: v304.8,16.51 296.27,25.04 294.23,25.04 D13.R2 | v436.07,138.43 435.66,138.43 419.4,154.69 419.4,156.31 417.78,157.94 AB04.BS1
  Bottom 0.203: v304.8,16.51 306.83,14.48 346.25,14.48 346.66,14.07 360.88,14.07 v361.29,13.66
DATA_ADD07  (via drill 0.61)
  Top 0.203: v397.46,103.07 397.05,103.48 397.05,146.96 v399.08,149
  Route15 0.203: v397.46,103.07 418.59,81.94 418.59,79.91 428.75,69.75 428.75,59.59 443.79,44.55 443.79,43.33 452.32,34.8 421.84,4.32 370.23,4.32 369.42,5.13 354.38,5.13 353.97,5.54 340.56,5.54 339.34,6.76 321.87,6.76 317.4,11.23 305.61,11.23 303.58,13.26 302.77,13.26 297.49,18.54 294.23,18.54 D13.T2
  Bottom 0.203: v399.08,149 401.12,151.03 407.62,151.03 410.46,153.87 415.34,153.87 416.56,152.65 416.97,152.65 AB04.BU1
DATA_ADD08  (via drill 0.61)
  Top 0.203: v341.38,3.91 341.38,1.07 295.86,1.07 294.64,2.29 294.64,11.23 293.83,12.04 D13.V2
  Route2 0.203: v396.24,9.2 396.24,10.01 432.82,46.58 432.82,47.4 440.54,55.12 v440.94,55.12 | v396.24,119.33 396.24,119.74 396.65,120.14 396.65,123.39 397.05,123.8 397.05,126.64 405.99,135.59 405.99,136.4 426.31,156.72 427.94,156.72 429.56,158.34 AB03.BS1
  Route15 0.203: v440.94,55.12 445.41,59.59 442.16,62.84 442.16,65.28 441.76,65.68 441.76,68.53 431.19,79.1 431.19,81.13 421.84,90.47 421.84,96.57 415.34,103.07 409.25,103.07 408.84,103.48 408.84,105.1 397.05,116.89 397.05,118.52 v396.24,119.33
  Bottom 0.203: v341.38,3.91 344.22,6.76 372.67,6.76 373.48,5.94 392.99,5.94 v396.24,9.2
DATA_ADD09  (via drill 0.61)
  Top 0.203: v340.16,220.12 339.75,219.71 v339.75,139.65 | v429.56,138.84 429.97,139.24 429.97,151.84 AB03.BU1
  Route2 0.203: v187.35,264.41 188.16,265.23 172.31,281.08 171.5,281.08 171.09,280.67 168.66,280.67 168.25,280.26 159.72,280.26 157.68,278.23 147.93,278.23 147.52,277.83 73.56,277.83 71.53,275.79 69.09,275.79 68.28,274.98 67.46,274.98 67.06,274.57 61.37,274.57 58.93,272.14 57.3,272.14 56.49,271.32 39.01,271.32 37.8,270.1 34.14,270.1 A34.B1
  Route15 0.203: v261.72,260.76 264.16,263.2 267,260.35 268.63,260.35 283.26,245.72 284.07,245.72 286.51,243.28 290.98,243.28 295.05,239.22 297.08,239.22 299.52,236.78 301.95,236.78 305.61,240.44 307.24,240.44 308.86,238.81 310.08,238.81 312.12,236.78 317.4,236.78 325.53,228.65 326.75,228.65 327.15,228.24 327.15,227.84 327.56,227.43 332.84,227.43 v340.16,220.12
  Bottom 0.203: v187.35,264.41 187.76,264.82 205.23,264.82 208.08,261.98 229.62,261.98 230.43,261.16 232.05,261.16 232.46,261.57 248.72,261.57 251.16,259.13 260.1,259.13 v261.72,260.76 | v339.75,139.65 340.16,140.06 422.25,140.06 423.47,138.84 v429.56,138.84
DATA_ADD10  (via drill 0.61)
  Top 0.203: v373.48,238.81 371.04,241.25 371.04,253.85 v367.79,257.1 | v166.62,252.63 165,254.25 165,260.76 149.15,276.61 112.17,276.61 112.17,282.3 111.76,282.7 109.32,282.7 v109.32,281.89 | v60.96,281.08 28.85,281.08 28.85,270.51 28.45,270.1 28.45,264.82 27.64,264.01 A34.D2
  Route2 0.203: v373.48,232.72 374.29,233.53 374.29,238 v373.48,238.81 | v254.41,281.08 251.97,281.08 v222.3,251.41
  Route15 0.203: v373.48,232.72 376.33,229.87 376.33,228.24 390.14,214.43 390.14,210.77 396.24,204.67 399.08,204.67 442.57,161.19 442.57,159.56 AB02.BS1 | v367.79,257.1 366.57,257.1 364.54,259.13 364.54,259.94 351.54,272.95 351.54,273.36 351.13,273.76 349.91,273.76 338.94,284.73 258.06,284.73 v254.41,281.08
  Bottom 0.203: v222.3,251.41 221.49,252.22 216.61,252.22 216.21,251.82 212.14,251.82 211.33,252.63 v166.62,252.63 | v109.32,281.89 108.51,281.08 v60.96,281.08
DATA_ADD11  (via drill 0.61)
  Top 0.203: v56.9,276.2 38.61,276.2 38.61,270.92 37.8,270.1 37.8,262.38 36.58,261.16 A34.E1
  Route2 0.203: v402.34,272.14 402.34,272.54 390.55,284.33 332.84,284.33 329.18,280.67 321.87,280.67 318.62,283.92 271.88,283.92 270.66,282.7 267.41,282.7 261.72,277.01 258.47,277.01 248.72,267.26 v248.31,267.26
  Route15 0.203: v402.34,272.14 v451.92,222.56 | v248.31,267.26 236.12,279.45 v235.71,279.45
  Bottom 0.203: v451.92,222.56 452.73,221.74 454.36,221.74 454.36,155.5 453.14,154.28 449.07,154.28 448.26,153.47 443.79,153.47 443.38,153.06 AB02.BU1 | v235.71,279.45 235.31,279.86 173.53,279.86 171.91,278.23 150.37,278.23 148.74,276.61 75.59,276.61 75.18,277.01 57.71,277.01 v56.9,276.2
DATA_ADD_EN
  Route15 0.203: A09.V2 345.03,218.49 349.5,218.49 351.13,216.86 351.54,216.86 361.29,207.11 362.1,207.11 362.51,206.7 366.98,206.7 386.89,186.79 386.89,185.57 403.15,169.32 403.15,164.44 405.18,162.41 405.18,161.19 406.4,159.97 406.4,157.53 407.62,156.31 AB04.BT2
  Bottom 0.203: 381.2,156.72 371.45,156.72 370.64,155.91 AB07.BT2 | 381.2,156.72 382.02,155.91 AB06.BT2 | 381.2,156.72 393.8,156.72 394.61,155.91 AB05.BT2 395.83,155.91 396.65,156.72 406.4,156.72 407.21,155.91 AB04.BT2 408.43,155.91 409.25,156.72 419.4,156.72 420.22,155.91 AB03.BT2 421.44,155.91 423.88,155.91 424.69,156.72 432,156.72 432.82,155.91 AB02.BT2
DATA_ENABLE  (via drill 0.61)
  Top 0.203: v358.85,215.24 v358.85,227.84
  Route15 0.203: v369.42,211.99 369.42,211.18 388.52,192.07 388.52,189.64 399.9,178.26 399.9,177.44 401.93,175.41 AB05.BL1
  Bottom 0.203: 425.5,173.38 415.75,173.38 414.93,174.19 AB04.BL1 413.71,174.19 413.31,173.79 408.84,173.79 408.43,173.38 400.3,173.38 | 425.5,173.38 426.31,174.19 AB03.BL1 | 425.5,173.38 438.51,173.38 439.32,174.19 AB02.BL1 | 387.71,173.38 377.55,173.38 376.73,174.19 AB07.BL1 | 387.71,173.38 388.52,174.19 AB06.BL1 | 400.3,173.38 401.12,174.19 AB05.BL1 | 387.71,173.38 400.3,173.38 | v358.85,227.84 355.19,227.84 354.79,228.24 A09.S1 | v358.85,215.24 359.26,215.65 365.76,215.65 v369.42,211.99
DATA_IN  (via drill 0.61)
  Top 0.203: v11.79,127.46 11.79,127.05 9.75,125.02 9.75,112.83 6.5,109.58 6.5,107.14 4.88,105.51 C36.M2 | v192.63,182.73 190.6,182.73 190.6,99.82 v191.01,99.42
  Route2 0.203: v11.79,127.46 22.76,138.43 24.38,138.43 33.73,147.78 34.14,147.78 47.14,160.78 47.14,161.19 52.83,166.88 53.24,166.88 53.65,167.28 53.65,169.32 55.27,170.94 B32.M2 | v331.62,235.97 334.47,238.81 334.47,240.84 A10.M2 | v242.21,227.03 227.58,212.39 226.37,212.39 216.61,202.64 215.8,202.64 195.88,182.73 v192.63,182.73
  Route15 0.203: v304.39,101.45 302.77,99.82 301.55,99.82 v301.14,100.23 | v129.24,105.1 131.27,107.14 110.95,127.46 110.95,127.86 100.79,138.02 98.75,138.02 v72.34,164.44
  Bottom 0.203: v304.39,101.45 306.02,103.07 317.81,103.07 318.62,102.26 C11.N2 | v301.14,100.23 291.8,100.23 290.98,101.04 288.95,101.04 288.14,100.23 268.22,100.23 266.6,98.6 266.6,96.57 225.96,96.57 225.55,96.98 191.01,96.98 | 191.01,96.98 162.15,96.98 158.9,100.23 134.11,100.23 v129.24,105.1 | v72.34,164.44 69.9,166.88 62.18,166.88 58.12,170.94 56.08,170.94 B32.M2 | v331.62,235.97 331.22,236.37 312.93,236.37 309.68,233.12 304.8,233.12 301.14,229.46 297.89,229.46 297.49,229.87 288.95,229.87 288.54,229.46 285.29,229.46 284.48,230.28 279.6,230.28 279.2,230.68 275.54,230.68 275.13,230.28 263.35,230.28 262.94,229.87 257.25,229.87 254.41,227.03 v242.21,227.03 | v191.01,99.42 191.01,96.98
DCA  (via drill 0.61)
  Top 0.203: v389.33,196.14 390.14,195.33 390.14,161.19 390.55,160.78 390.55,138.43 390.14,138.02 390.14,119.33 v389.74,118.92 | v358.85,20.98 361.29,20.98 361.29,21.39 361.7,21.79 361.7,36.42 358.44,39.68 358.44,69.75 358.04,70.16 358.04,71.78 358.44,72.19 358.44,86 v358.04,86.41
  Route2 0.203: v389.74,118.92 389.74,118.52 382.83,111.61 382.83,110.39 379.98,107.54 379.98,107.14 | 379.98,107.14 379.98,105.92 379.58,105.51 C07.M1 | v358.04,86.41 375.51,103.89 376.73,103.89 379.98,107.14
  Route15 0.203: v389.33,196.14 357.23,228.24 357.23,229.46 356.82,229.87 356.41,229.87 338.94,247.34 338.94,248.97 338.53,249.38 337.72,249.38 329.18,257.91 328.37,257.1 328.37,255.88 328.78,255.47 329.18,255.47 331.22,253.44 331.22,251.41 A10.J2
  Bottom 0.203: v358.85,20.98 349.1,20.98 348.29,21.79 D09.S2
DCA\  (via drill 0.61)
  Top 0.203: C09.M2 347.47,105.51 347.47,106.32 v347.07,106.73 347.07,107.14 347.07,107.95 v349.1,109.98
  Route2 0.203: v318.62,105.51 308.86,95.76 306.83,95.76 C12.R2
  Bottom 0.203: v318.62,105.51 319.02,105.92 337.31,105.92 337.72,106.32 346.66,106.32 v347.07,106.73 | v349.1,109.98 355.19,109.98 355.6,109.58 374.29,109.58 375.51,108.36 C07.L1
DEFER  (via drill 0.61)
  Top 0.203: A10.C1 341.78,266.04 342.6,265.23 342.6,251 339.75,248.16 339.75,240.03 338.53,238.81 A10.N1 | v300.74,97.38 301.55,96.57 301.55,88.04 v301.14,87.63 | v366.17,87.63 366.57,88.04 366.57,91.29 C08.S1
  Route2 0.203: v284.07,238.4 271.88,226.21 271.07,226.21 259.69,214.83 259.28,214.83 257.66,213.21 257.66,211.99 227.99,182.32 227.99,180.7 v227.58,180.29
  Route15 0.203: v227.58,180.29 227.58,179.07 231.65,175.01 231.65,170.13 251.97,149.81 251.97,148.59 255.22,145.34 255.22,143.31 300.74,97.79 v300.74,97.38
  Bottom 0.203: A12.C1 316.59,266.85 316.99,267.26 320.65,267.26 321.46,268.07 339.34,268.07 340.56,266.85 A10.C1 | A10.N1 337.72,237.59 334.87,237.59 334.06,236.78 305.61,236.78 304.39,238 300.74,238 A13.N1 299.52,237.59 298.7,236.78 285.7,236.78 v284.07,238.4 | v300.74,97.38 300.33,96.98 279.6,96.98 278.38,98.2 C15.P1 | v301.14,87.63 301.95,88.44 304.8,88.44 305.61,87.63 349.1,87.63 350.32,86.41 351.54,86.41 352.75,87.63 v366.17,87.63
DEFER\  (via drill 0.61)
  Top 0.203: v315.37,70.97 314.15,69.75 314.15,59.18 312.93,57.96 D12.D1
  Route2 0.203: v343.81,78.28 344.22,78.28 v351.54,85.6
  Route15 0.203: v397.46,57.96 368.61,86.82 368.61,87.22 368.2,87.63 367.39,87.63 366.57,86.82 366.98,86.41 C08.U1
  Bottom 0.203: v315.37,70.97 321.06,76.66 342.19,76.66 v343.81,78.28 | v351.54,85.6 353.16,87.22 364.95,87.22 366.17,86 C08.U1 | v397.46,57.96 397.87,58.37 403.96,58.37 406.4,55.93 421.44,55.93 421.84,56.34 425.5,56.34 425.91,55.93 440.13,55.93 440.54,56.34 443.38,56.34 443.79,55.93 447.04,55.93 448.67,54.3 D01.E2
DOUBLE_LEFT_ROTATE  (via drill 0.61)
  Top 0.203: v338.53,151.84 336.5,153.87 336.5,167.28 337.72,168.5 B10.N1 | v358.85,185.98 358.85,199.8 361.7,202.64 361.7,206.7 359.26,209.14 359.26,214.43 361.7,216.86 361.7,223.77 360.88,224.59 360.88,225.4 362.51,227.03 362.51,230.68 362.1,231.09 362.1,233.12 362.51,233.53 362.51,237.19 362.1,237.59 362.1,240.03 v363.73,241.66
  Route2 0.203: v358.85,185.98 348.69,175.82 348.29,175.82 340.97,168.5 338.94,168.5 B10.N1 | v363.73,241.66 364.13,241.66 375.11,252.63 377.55,252.63 378.76,253.85 AB07.AH1
  Route15 0.203: v338.53,151.84 340.97,149.4 343.81,149.4 B09.V2
  Bottom 0.203: AB02.AH1 442.16,253.85 438.51,253.85 437.29,252.63 431.6,252.63 430.78,253.44 AB03.AH1 429.56,253.85 428.35,252.63 419.4,252.63 418.19,253.85 AB04.AH1 416.97,253.44 413.31,253.44 412.5,252.63 406.81,252.63 | AB07.AH1 379.98,253.44 380.8,252.63 386.89,252.63 388.11,253.85 391.36,253.85 AB06.AH1 392.58,253.44 393.39,252.63 406.81,252.63 | 406.81,252.63 405.59,253.85 AB05.AH1
DOUBLE_RIGHT_ROTATE  (via drill 0.61)
  Top 0.203: B09.J2 344.22,181.51 343.81,181.91 v343.81,185.57 344.22,185.57 346.25,185.57 346.25,193.29 349.1,196.14 v349.1,204.27 | v377.14,235.15 377.55,235.56 377.55,261.57 376.33,262.79 AB07.AD1
  Route2 0.203: v349.1,204.27 349.1,206.3 351.94,209.14 351.94,209.96 v377.14,235.15
  Bottom 0.203: v343.81,185.57 342.19,187.2 338.94,187.2 B10.F1 | 388.11,262.38 377.55,262.38 376.73,263.2 AB07.AD1 | 388.11,262.38 388.52,262.79 AB06.AD1 | 400.3,262.38 401.12,263.2 AB05.AD1 | 388.11,262.38 400.3,262.38 | 412.9,262.38 413.71,263.2 AB04.AD1 | 400.3,262.38 412.9,262.38 | 425.5,262.38 426.31,263.2 AB03.AD1 | 412.9,262.38 425.5,262.38 | 425.5,262.38 438.91,262.38 439.32,262.79 AB02.AD1
E_SET  (via drill 0.61)
  Top 0.203: v350.72,87.22 350.72,83.16 C09.V1 | v357.23,91.69 357.23,89.66 C08.T2
  Bottom 0.203: v350.72,87.22 351.13,87.63 351.94,87.63 352.75,88.44 356.82,88.44 C08.T2 | v357.23,91.69 358.44,90.47 366.98,90.47 367.79,91.29 371.45,91.29 372.26,92.1 C07.S2
E_SET\  (via drill 0.61)
  Top 0.203: D17.T2 243.43,18.54 243.43,18.14 245.47,16.1 D17.U2 246.28,15.29 246.69,14.88 v246.69,4.72 | v312.52,178.66 314.15,177.04 314.15,160.38 v313.74,159.97 | v332.44,157.12 333.25,156.31 333.25,139.65 332.03,138.43 332.03,135.18 333.25,133.96 333.25,131.12 v331.22,129.08 | v370.64,5.13 371.04,5.54 371.04,66.09 369.42,67.72 369.42,79.91 371.04,81.53 371.04,83.57 370.23,84.38 370.23,88.44 C07.T2
  Route15 0.203: C07.T2 369.82,89.66 369.82,91.69 364.95,96.57 364.95,97.38 353.97,108.36 353.16,108.36 336.09,125.42 335.28,125.42 332.44,128.27 330.81,128.27 329.18,129.9 C11.C1 | v312.52,178.66 311.3,179.88 311.3,185.17 300.33,196.14 300.33,199.39 B13.B1
  Bottom 0.203: C11.D2 319.84,127.05 321.46,128.68 326.75,128.68 327.96,129.9 C11.C1 329.18,129.9 330.4,129.9 v331.22,129.08 | v313.74,159.97 326.34,159.97 327.15,159.16 327.15,157.12 v332.44,157.12 | v246.69,4.72 248.31,4.72 248.72,5.13 260.1,5.13 261.31,3.91 293.01,3.91 293.83,4.72 295.05,4.72 295.45,5.13 300.33,5.13 302.77,2.69 343.81,2.69 345.85,4.72 353.16,4.72 353.57,5.13 v370.64,5.13
EA\  (via drill 0.61)
  Route2 0.203: D16.C1 265.79,60.81 265.79,65.28 291.8,91.29 291.8,92.91 293.42,94.54 C13.R2
  Route15 0.203: v56.49,198.17 79.25,175.41 79.25,170.94 102.41,147.78 104.85,147.78 121.92,130.71 122.73,130.71 124.77,128.68 126.8,128.68 128.02,127.46 C26.D2 128.83,126.24 130.45,124.61 130.45,122.99 165.41,88.04 v165.41,87.63 | v241.81,86 242.21,86 264.57,63.65 264.57,60.81 D16.C1
  Bottom 0.203: v56.49,198.17 35.76,198.17 34.14,199.8 B34.B1 | v241.81,86 240.18,87.63 v165.41,87.63
EMA\  (via drill 0.61)
  Route2 0.203: v26.42,170.94 15.44,159.97 15.44,154.69 14.63,153.87 14.63,149.81 B35.V2 | v68.68,175.01 68.68,175.41 69.9,176.63 69.9,177.44 106.07,213.61 106.07,214.02 107.29,215.24 108.1,215.24 v114.2,221.34 | v306.43,210.77 306.43,211.18 310.08,214.83 310.49,214.83 311.3,215.65 313.74,215.65 314.15,215.24 317.4,215.24 326.75,224.59 326.75,227.03 327.15,227.43 327.15,229.06 369.42,271.32 v372.67,271.32
  Route15 0.203: v286.51,217.68 296.67,217.68 299.52,214.83 302.36,214.83 v306.43,210.77
  Bottom 0.203: v26.42,170.94 28.45,172.97 47.14,172.97 47.55,172.57 48.36,172.57 49.17,173.38 67.06,173.38 v68.68,175.01 | v114.2,221.34 116.64,223.77 166.22,223.77 172.31,217.68 253.19,217.68 253.59,218.08 254.41,218.08 254.81,217.68 v286.51,217.68 | v372.67,271.32 390.55,271.32 390.96,271.73 401.52,271.73 401.93,271.32 446.63,271.32 451.1,266.85 451.1,257.91 452.32,257.91 A01.F1
ENABLE\  (via drill 0.61)
  Top 0.203: v88.19,179.48 88.59,179.88 88.59,221.74 92.25,225.4 92.25,245.72 93.47,246.94 AB29.AK2
  Bottom 0.203: v88.19,179.48 88.59,179.48 88.59,177.04 88.19,176.63 82.5,176.63 81.69,177.44 AB30.BK2
EXECUTE
  Top 0.203: B09.J1 350.32,181.51 350.32,186.79 B09.F1 | B09.H1 353.57,183.54 353.57,178.26 B09.K1 354.38,177.04 355.6,175.82 355.6,83.57 356.41,82.75 C08.V2
  Bottom 0.203: B09.F1 351.54,187.2 351.94,186.79 354.79,186.79 355.19,186.38 355.19,184.76 354.38,184.76 B09.H1
EXECUTE\  (via drill 0.61)
  Top 0.203: v366.98,78.28 366.98,78.69 363.73,81.94 C08.V1
  Route2 0.203: v396.65,78.69 400.3,82.35 400.3,83.16 v414.53,97.38
  Bottom 0.203: v366.98,78.28 367.39,77.88 381.2,77.88 382.02,78.69 388.93,78.69 389.74,77.88 395.43,77.88 396.24,78.69 v396.65,78.69 | v414.53,97.38 414.93,96.98 447.85,96.98 447.85,91.29 445.01,91.29 443.79,90.07 438.91,90.07 438.51,89.66 438.51,87.22 447.45,87.22 448.67,86 C01.U2
F_SET  (via drill 0.61)
  Top 0.203: v355.19,50.65 355.6,51.05 355.6,77.88 355.19,78.28 v355.19,82.75
  Route2 0.203: v355.19,82.75 355.19,85.19 358.44,88.44 358.44,92.1 366.17,99.82 368.2,99.82 369.42,101.04 C07.N2 | v242.21,128.68 242.62,128.68 251.97,138.02 252.78,138.02 254.41,139.65 255.22,139.65 266.6,151.03 267.41,151.03 287.32,170.94 287.32,171.75 v287.73,172.16 301.95,186.38 301.95,189.23 302.77,190.04 B13.E1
